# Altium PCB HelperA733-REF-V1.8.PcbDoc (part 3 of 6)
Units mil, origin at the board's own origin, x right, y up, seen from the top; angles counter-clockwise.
Board outline 5905.51 x 4133.86 mil, 2 copper layers (Top, Bottom), stack 12.7 mil thick; 475 components, 355 nets, 1867 pads, 1471 vias.
Unrouted connection lines stored in the file: 1178.
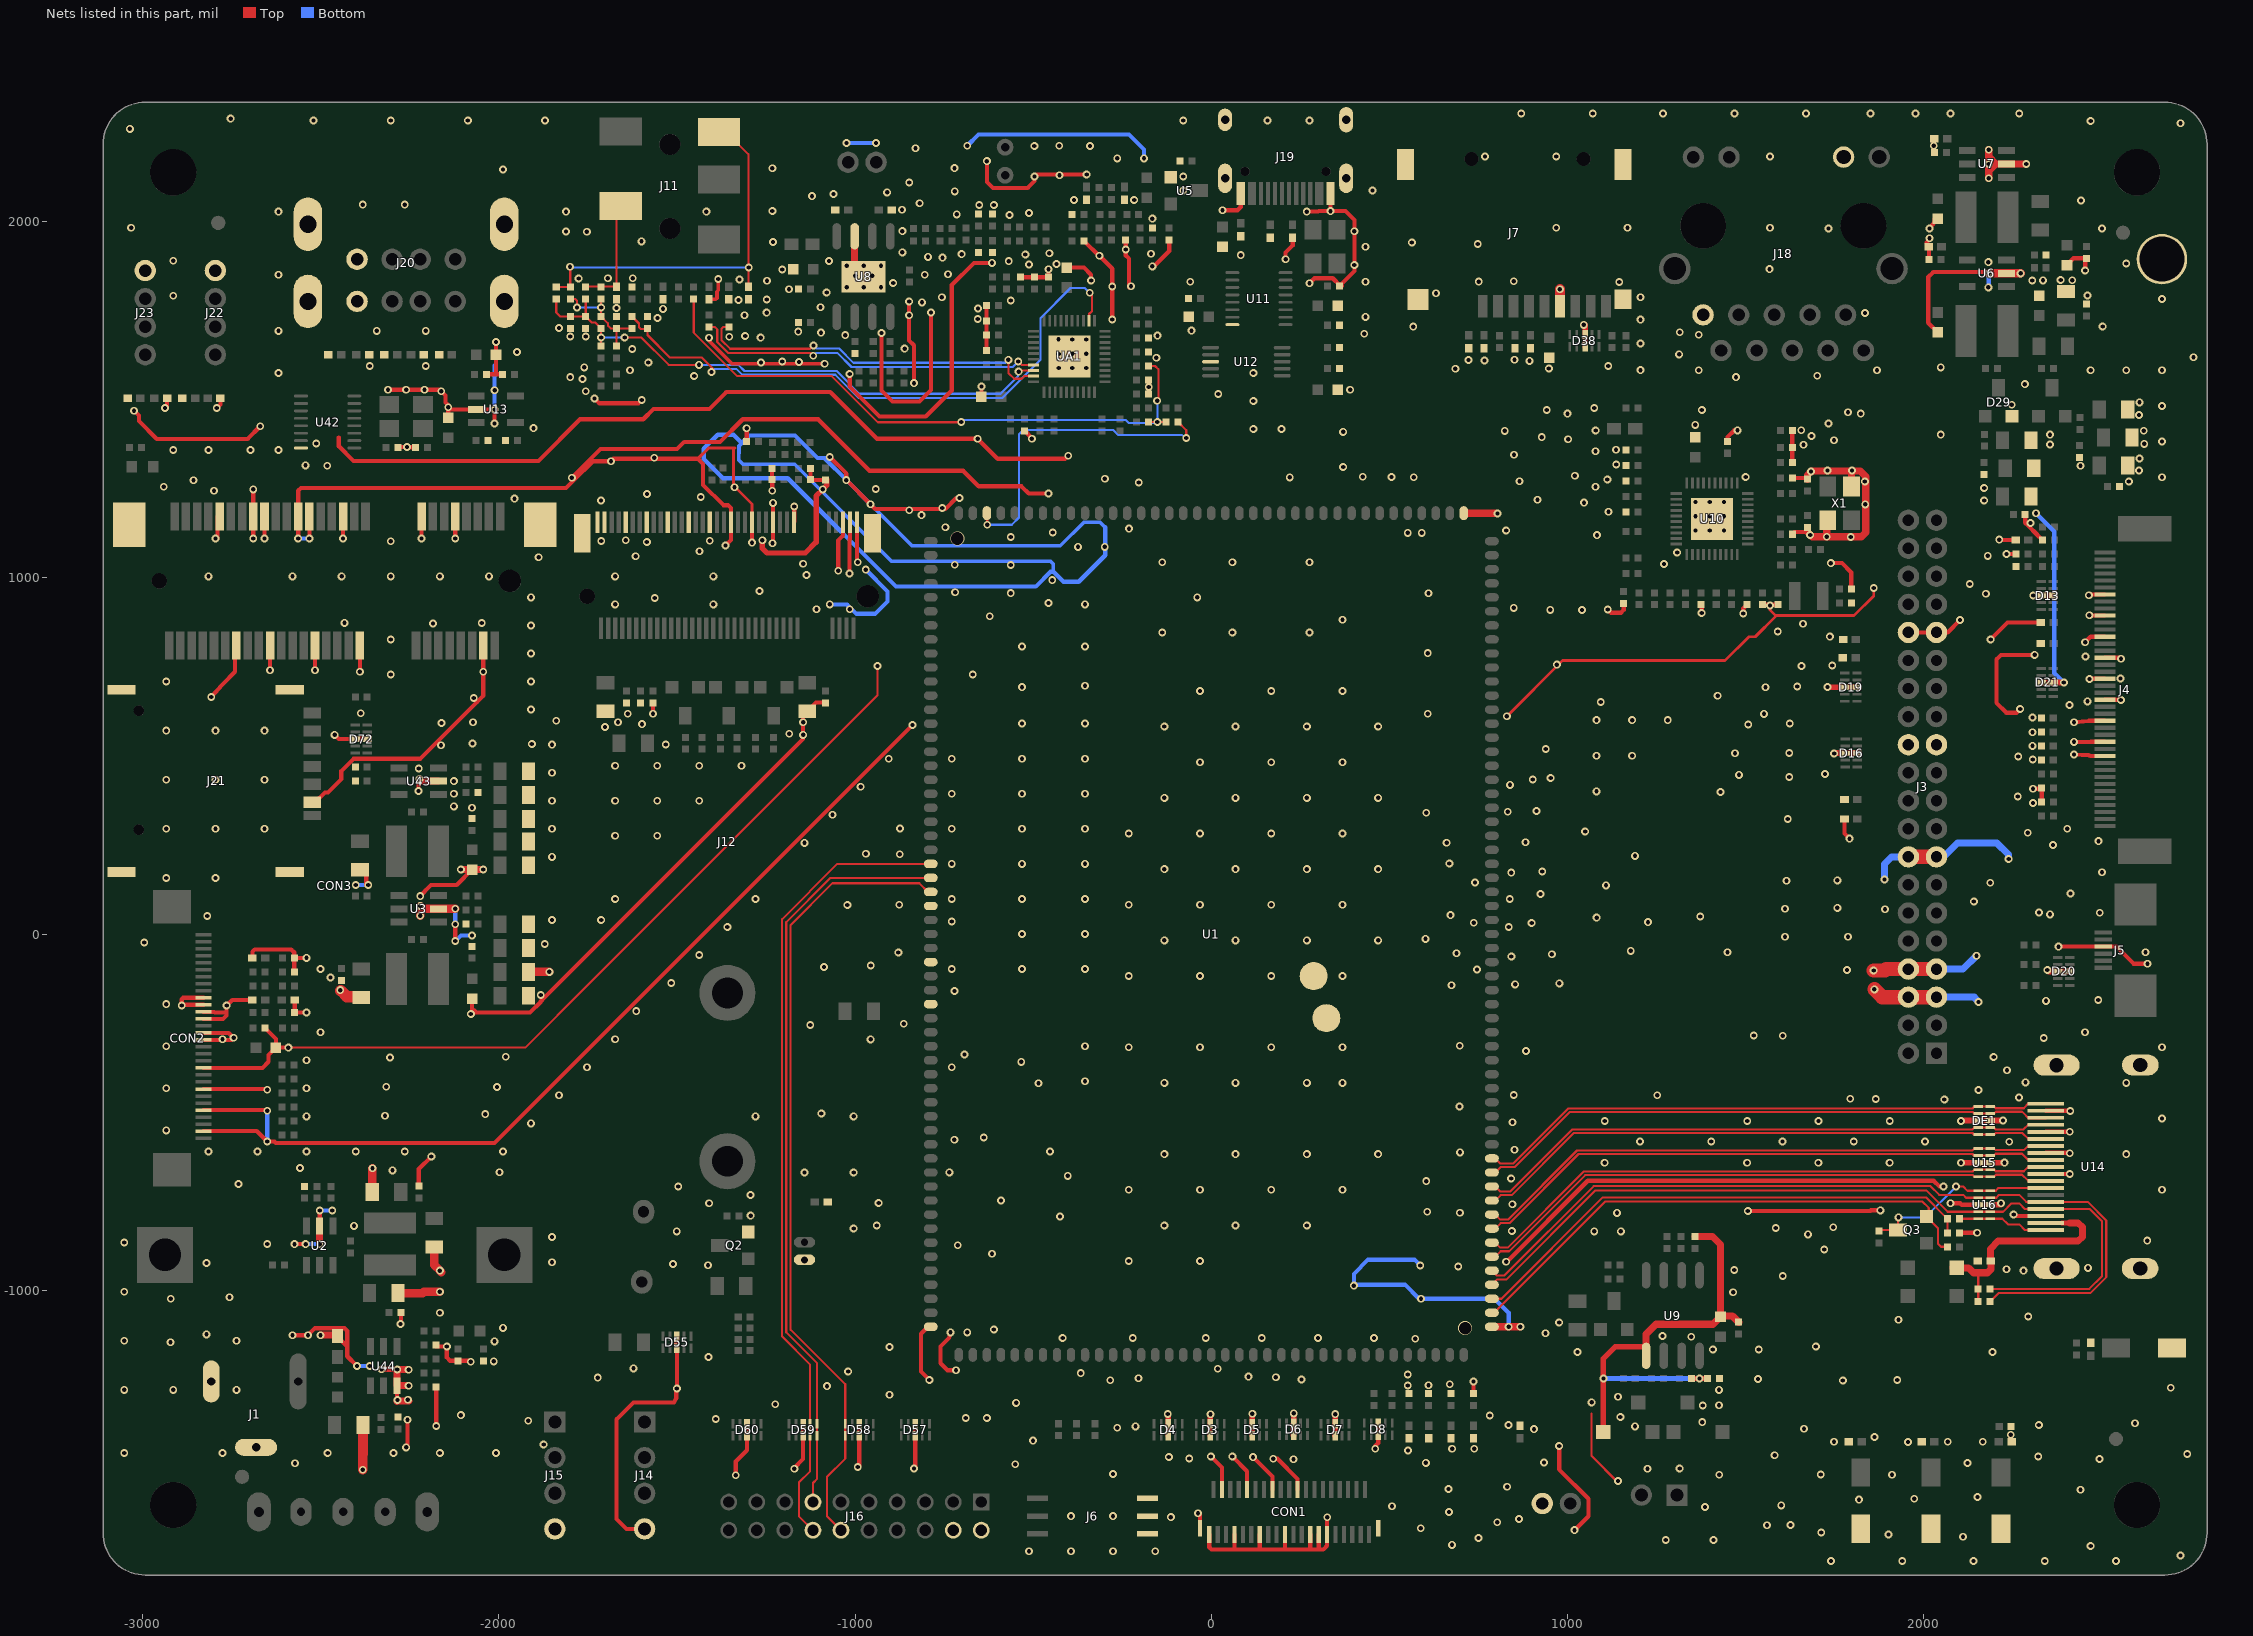
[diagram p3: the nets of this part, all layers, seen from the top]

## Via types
v1: diameter 22, hole 12, Top to Bottom, 1469 vias
v2: diameter 39.37, hole 35.43, Top to Bottom, 2 vias

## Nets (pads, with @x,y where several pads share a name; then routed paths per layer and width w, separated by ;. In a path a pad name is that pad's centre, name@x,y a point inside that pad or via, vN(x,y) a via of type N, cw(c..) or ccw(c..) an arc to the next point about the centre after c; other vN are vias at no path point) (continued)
GND: C2.2 C3.2 C5.2 C6.2 C7.2 C9.2 C10.2 C12.2 C13.2 C19.1 C20.1 C26.1 C27.2 C30.2 C31.2 C32.2 C33.1 C34.2 C35.2 C37.1 C38.2 C39.2 C40.2 C41.2 C42.2 C43.2 C44.2 C45.1 C46.2 C47.2 C49.2 C51.2 C54.1 C57.2 C58.2 C62.1 C63.1 C64.2 C65.2 C66.2 C67.2 C68.2 C69.2 C70.2 C71.2 C84.2 C86.2 C87.2 C88.2 C90.2 C91.2 C93.2 C94.2 C95.2 C96.2 C97.2 C98.2 C99.2 C100.2 C101.2 C102.2 C103.2 C323.1 C324.2 CA1.1 CA2.2 CA3.1 CA4.1 CA5.1 CA10.2 CA11.2 CA12.2 CA13.2 CA14.2 CA15.2 CA16.1 CA17.2 CA18.2 CA20.1 CA26.2 CB1.1 CB2.1 CB3.1 CB6.1 CB7.1 CB8.1 CB9.1 CE1.1 CE2.1 CE3.1 CE4.1 CE5.1 CE6.1 CE7.1 CE8.1 CE9.1 CE10.1 CE11.1 CE12.1 CE13.1 CE14.1 CE15.1 CL1.2 CON1.1 CON1.4 CON1.7 CON1.10 CON1.13 CON1.16 CON1.19 CON1.22 CON1.25 CON1.27 CON1.29 CON1.40 CON1.41 CON2.2 CON2.5 CON2.8 CON2.11 CON2.15 CON2.16 CON2.18 CON2.19 CON2.20 CON2.21 CON3.4 CON3.9 CON3.15 CON3.18 CON3.21 CON3.26 CON3.27 CON3.29 CON3.34 CON3.35 CON3.37 CON3.40 CON3.43 CON3.M1 CON3.M2 CP1.2 CP2.2 CP3.2 CP4.2 CU1.1 CU2.1 CU3.1 D3.3 D3.8 D4.3 D4.8 D5.3 D5.8 D6.3 D6.8 D7.3 D7.8 D8.3 D8.8 D9.1 D10.1 D11.1 D12.1 D13.3 D13.8 D15.1 D16.3 D16.8 D17.1 D18.1 D19.3 D19.8 D20.3 D20.8 D21.3 D21.8 D22.2 D23.2 D24.2 D25.2 D27.1 D28.2 D29.2 D30.2 D33.1 D34.1 D35.1 D36.1 D37.1 D38.3 D38.8 D39.2 D40.1 D41.1 D42.2 D43.1 D44.1 D45.1 D46.1 D47.1 D48.1 D49.1 D50.1 D55.3 D55.8 D57.3 D57.8 D58.3 D58.8 D59.3 D59.8 D60.3 D60.8 D61.2 D62.2 D63.2 D64.1 D65.2 D66.2 D67.2 D68.2 D71.2 D72.3 D72.8 D76.2 D77.2 D78.2 D79.2 D80.2 D81.2 D82.2 D83.2 DA1.1 DA2.1 DE1.3 DE1.8 FID5.1 J1.2 J1.3 J3.5 J3.6 J3.7 J3.8 J3.15 J3.16 J3.23 J3.24 J3.31 J3.32 J4.7 J4.10 J4.13 J4.16 J4.19 J4.22 J4.25 J4.28 J4.30 J5.3 J6.4 J6.5 J6.6 J7.6 J7.10 J7.11 J7.12 J7.13 J8.1 J9.2 J12.1 J12.3 J12.9 J12.15 J12.21 J12.27 J12.33 J12.39 J12.45 J12.51 J12.57 J12.71 J12.73 J12.75 J12.76 J12.77 J14.4 J15.4 J16.2 J16.4 J18.10 J18.12 J19.13 J19.14 J19.15 J19.16 J19.A1 J19.B1 J20.4 J20.8 J20.9 J20.10 J20.11 J20.12 J21.5 J21.8 J21.9 J21.10 J21.11 J22.1 J23.1 K1.2 K2.1 K3.1 K4.2 Q2.2 R6.1 R7.2 R11.2 R18.2 R20.1 R32.1 R34.2 R35.2 R36.2 R37.1 R41.1 R42.2 R43.2 R44.2 R45.2 R46.2 R47.2 R55.1 R65.2 R67.2 R75.2 R83.1 R92.2 R116.2 R118.2 R156.2 R158.2 R234.2 R235.2 R239.1 R241.1 R333.2 R334.2 RA2.1 RA4.2 RA12.2 RA26.2 RA27.2 RA30.1 RE4.1 RE14.1 RE15.1 RL2.1 RU1.1 RU2.1 U1.38 U1.95 U1.158 U1.162 U1.165 U1.188 U1.189 U1.190 U2.2 U3.2 U5.1 U6.2 U7.2 U8.7 U8.9 U10.41 U11.8 U12.3 U13.2 U14.2 U14.5 U14.8 U14.11 U14.17 U14.20 U14.21 U14.22 U14.23 U15.3 U15.8 U16.3 U16.8 U42.8 U43.2 U44.6 UA1.41 X1.2 X1.4 | length 44515.1
  Top w5: v1(-428.85,1669.23) -398.43,1638.81 UA1.41@-398.43,1621.09
  Top w6: v1(-2590.55,-318.9) -1925.2,-318.9 -1834.65,-228.35 -1834.65,-227.53 -937.01,670.1 v1(-937.01,751.97) ; 1067.52,-1346.23 1067.52,-1465.16 1141.73,-1539.37 v1(1141.73,-1535.43)
  Top w8: -1441.22,1333.93 -1410.74,1364.41 -1341.13,1364.41 ; -1336.41,1364.41 -1341.13,1364.41 ; J12.45@-1289.37,1155.5 -1289.37,1207.05 -1341.13,1258.81 -1341.13,1364.41 ; v1(829.64,611.41) 985.57,767.34 1010.2,767.34 1442.33,767.33 1509.16,834.16 1526.77,834.16 1583.87,891.26 1583.87,893.66 ; v1(1568.32,922.2) 1568.32,909.2 1583.87,893.66 ; v1(1859.19,971.14) 1859.19,948.77 1804.08,893.66 1583.87,893.66
  Top w10: v1(-1409.87,1673.56) -1409.87,1664.87 -1345.47,1600.47 v1(-1085.28,1600.47) ; D48.1@-1409.45,1781.21 -1390.96,1781.21 -1387.33,1784.84 -1387.33,1802.85 -1383.63,1806.55 -1383.63,1838.57 v1(-1383.86,1838.8) ; v1@-1353.3,1677.14 -1352.97,1676.81 v1(-1352.97,1676.48)
  Top w11.81: v1(-3023.62,1468.5) -3010.13,1455.01 -3010.13,1439.89 -2960,1389.76 -2704.72,1389.76 v1(-2669.29,1425.2) ; v1(-2937.01,1476.38) -2935.04,1474.41 -2930.82,1478.63 D78.2@-2930.82,1503.94 ; CON2.2@-2828.74,-553.15 -2679.13,-553.15 v1(-2649.61,-582.68) -2629.62,-582.68 -2625.68,-586.61 -2011.81,-586.61 v1(-838.58,586.61) ; CON2.5@-2828.74,-494.09 -2647.64,-494.09 v1(-2649.61,-496.06) ; CON2.8@-2828.74,-435.04 -2647.64,-435.04 v1(-2649.61,-437.01) ; CON2.11@-2828.74,-375.98 -2663.41,-375.98 -2646.12,-358.7 -2646.12,-339.43 C27.2@-2625.59,-318.9 ; CON2.15@-2828.74,-297.24 -2750,-297.24 v1(-2744.09,-291.34) -2757.87,-277.56 CON2.16@-2828.74,-277.56 ; CON2.18@-2828.74,-238.19 -2773.62,-238.19 -2763.78,-228.35 -2763.78,-220.47 ; CON2.19@-2828.74,-218.5 -2799.2,-218.5 -2797.23,-220.47 -2763.78,-220.47 ; CON2.20@-2828.74,-198.82 -2887.8,-198.82 v1(-2889.76,-200.79) -2889.76,-183.07 -2885.83,-179.13 CON2.21@-2828.74,-179.13 ; v1(-2807.09,665.35) -2775.59,700.56 -2740.16,735.99 -2740.16,810.04 CON3.40@-2736.22,810.04 ; v1(-2795.28,1110.24) -2789.46,1110.24 -2789.46,1172.24 CON3.43@-2783.47,1172.24 ; v1(-2791.34,1476.38) -2781.21,1486.5 D76.2@-2781.21,1503.94 ; D15.1@-2691.23,-185.04 -2748.03,-185.04 v1(-2763.78,-200.79) -2763.78,-220.47 ; D18.1@-2691.23,-66.93 -2691.23,-49.5 -2685.04,-43.31 -2582.68,-43.31 -2574.8,-51.18 -2573.82,-51.18 RL2.1@-2573.82,-66.93 ; v1(-2688.98,1110.24) v1(-2688.98,1248.03) ; v1(-2657.48,1110.24) CON3.35@-2657.48,1172.24 ; C26.1@-2656.5,-263.78 -2625.59,-294.69 C27.2@-2625.59,-318.9 ; v1(-2641.73,740.16) CON3.34@-2641.73,810.04 ; v1(-2590.55,-318.9) C27.2@-2625.59,-318.9 ; v1(-2578.74,-1125.98) v1(-2535.43,-1125.98) -2515.75,-1106.3 -2433.07,-1106.3 -2425.1,-1114.27 -2425.1,-1157.57 ; R20.1@-2573.82,-220.47 R20.1@-2572.55,-220.47 ; CL1.2@-2573.82,-106.3 RL2.1@-2573.82,-66.93 ; v1(-2573.43,-870.46) v1(-2541.93,-870.46) ; D17.1@-2572.55,-185.04 R20.1@-2572.55,-220.47 ; v1(-2562.99,1110.24) CON3.29@-2562.99,1172.24 -2562.99,1244.09 -2555.12,1251.97 -1811.02,1251.97 -1788.55,1274.45 -1736.22,1326.77 v1(-1685.04,1326.77) -1677.88,1333.93 -1441.22,1333.93 -1426.29,1319 -1426.29,1260.69 -1369.33,1203.73 -1356.65,1203.73 -1348.43,1195.51 J12.39@-1348.43,1155.5 -1348.43,1105.66 v1(-1363.54,1090.55) ; v1(-2539.37,-220.47) R20.1@-2572.55,-220.47 ; v1(-2539.37,-66.93) RL2.1@-2573.82,-66.93 ; v1(-2531.5,1110.24) CON3.27@-2531.5,1172.24 ; J21.5@-2523.62,370.08 -2515.16,370.08 -2487.65,397.59 -2478.97,397.59 -2441.79,434.77 -2441.79,457.31 -2407.38,491.72 -2220.59,491.72 -2060.14,652.17 -2043.31,669.01 v1(-2043.31,736.22) CON3.4@-2043.31,810.04 ; v1(-2515.75,740.16) CON3.26@-2515.75,810.04 ; U2.2@-2502.56,-819.28 v1(-2502.56,-775.97) ; v1(-2460.63,559.06) -2448.82,547.24 D72.8@-2402.87,547.24 -2402.87,549.21 -2368.79,549.21 D72.3@-2368.79,547.24 ; R156.2@-2452.76,-1125.98 -2452.76,-1129.92 -2425.1,-1157.57 ; -2448.82,1393.7 -2448.82,1369.13 -2407.64,1327.95 -1888.58,1327.95 -1771.65,1444.88 -1594.46,1444.88 -1565.5,1473.84 -1408.66,1473.83 -1361.26,1521.23 -1069.51,1521.23 -938.45,1390.17 v1(-655.88,1390.17) -599.47,1333.76 -410.33,1333.76 v1(-401.57,1342.52) ; v1(-2444.88,-157.48) v1@-2443.24,-159.13 ; v1(-2437.01,1110.24) CON3.21@-2437.01,1172.24 ; v1(-2397.64,-1212.6) -2425.1,-1185.13 -2425.1,-1157.57 ; C90.2@-2389.76,180.47 -2371.72,180.47 -2371.72,137.8 v1(-2366.14,137.8) ; v1(-2389.76,736.22) CON3.18@-2389.76,810.04 ; v1(-2311.02,1527.56) v1(-2259.84,1527.56) v1@-2212.6,1527.56 ; U44.6@-2285.43,-1267.72 -2285.43,-1311.5 -2285.43,-1312.53 v1(-2284.2,-1308.18) v1@-2284.16,-1311.26 ; C86.2@-2282.48,1366.14 -2282.48,1366.86 v1(-2257.56,1366.86) -2256.84,1366.14 C87.2@-2233.27,1366.14 ; v1(-2275.59,-1094.49) -2274.61,-1093.5 C3.2@-2274.61,-1062.99 ; v1(-2259.84,-1440.94) -2256.04,-1437.01 v1(-2256.04,-1363.52) ; v1(-2225.4,401.26) -2225.4,428.15 -2224.41,429.13 v1(-2222.31,435.5) ; C7.2@-2224.41,-707.68 -2224.41,-659.78 v1(-2189.19,-624.56) ; v1(-2220.47,106.3) -2206.67,120.1 -2206.67,121.19 -2190.07,137.8 -2117.72,137.8 C94.2@-2074.8,180.71 ; v1(-2216.54,1110.24) CON3.15@-2216.54,1172.24 ; -2213.86,-1007.87 -2209.92,-1003.94 ; R239.1@-2176.18,-1271.65 -2176.18,-1283.31 -2175.62,-1283.87 v1(-2175.62,-1380.63) ; R158.2@-2176.18,-1153.54 -2176.18,-1157.48 v1(-2145.67,-1157.48) -2145.67,-1188.98 -2136.81,-1197.83 R6.1@-2114.17,-1197.83 -2081.69,-1197.83 v1(-2078.74,-1200.79) ; C84.2@-2141.73,1449.21 v1(-2141.73,1478.56) ; v1(-2122.05,-19.69) v1(-2122.05,27.56) ; v1(-2122.05,1110.24) CON3.9@-2122.05,1172.24 ; v1(-2078.2,-224.25) v1@-2074.8,-220.86 ; C13.2@-2074.8,-181.5 -2074.8,-208.66 ; CU3.1@-2034.45,1570.87 -2003.94,1570.87 ; v1(-2011.81,1433.07) -2011.54,1433.34 v1(-2011.54,1472.44) U13.2@-2062.99,1472.44 -2135.61,1472.44 v1(-2141.73,1478.56) ; v1(-2007.87,1661.42) CU2.1@-2007.48,1625.98 -2007.48,1574.41 -2003.94,1570.87 ; CU1.1@-1989.17,1570.87 -2003.94,1570.87 ; v1(-1794.84,1280.74) -1714.48,1361.1 -1499.52,1361.1 -1479.54,1381.08 -1378.68,1381.08 -1315.03,1444.72 -1103.4,1444.72 -959.03,1300.35 -696.46,1300.35 -652.67,1256.56 -532.62,1256.56 -512.28,1236.22 v1(-456.69,1236.22) ; v1(-1731.1,1502.89) -1718.18,1489.97 -1607.43,1489.97 v1(-1598.49,1498.91) ; J14.4@-1590.55,-1669.69 -1641.34,-1669.69 -1669.29,-1641.73 -1669.29,-1362.2 -1622.05,-1314.96 -1507.87,-1314.96 -1501.97,-1303.15 -1501.97,-1277.56 v1(-1500,-1275.59) D55.8@-1500,-1162.71 -1501.97,-1162.71 -1501.97,-1128.63 D55.3@-1500,-1128.63 ; v1(-1566.93,618.11) CB6.1@-1566.93,648.62 ; v1(-1334.62,-1518.94) -1334.62,-1480.39 -1303.15,-1448.92 D60.8@-1303.15,-1408.38 D60.3@-1303.15,-1374.3 ; CB9.1@-1304.13,1381.89 v1(-1304.13,1419.73) ; v1(-1289.42,1098.49) -1289.37,1116.48 J12.45@-1289.37,1155.5 ; R234.2@-1233.27,1307.09 R334.2@-1233.27,1275.59 -1233.27,1268.21 -1232.28,1267.22 v1(-1232.28,1244.09) ; v1(-1231.36,1096.76) -1230.32,1096.76 J12.51@-1230.32,1155.5 v1(-1230.32,1210.13) ; J12.57@-1171.26,1155.5 -1171.26,1157.48 -1170.61,1157.48 v1(-1170.61,1200.14) ; v1(-1170.25,-1500.8) -1170.25,-1498.07 -1145.67,-1473.49 D59.8@-1145.67,-1408.38 D59.3@-1145.67,-1374.3 ; R235.2@-1125,1307.09 R333.2@-1125,1275.59 -1124.02,1274.61 CB8.1@-1082.68,1274.61 ; CB1.1@-1082.68,648.62 -1082.68,649.76 -1109.45,649.76 CB3.1@-1133.86,625.35 -1140.73,625.35 -1145.67,620.42 v1(-1145.67,594.49) v1(-1145.67,559.06) -1145.67,547.24 -1872.88,-179.96 -1881.89,-188.98 -1881.89,-190.28 -1912.09,-220.47 -2062.99,-220.47 ; v1(-1070.87,1338.58) -1024.43,1292.15 v1(-1024.43,1273.9) v1(-956.66,1206.13) -943.41,1192.88 -746.55,1192.88 -716.01,1223.42 v1(-706.75,1223.57) ; v1(-1047.24,1019.68) -1047.29,1104.2 -1033.47,1118.02 J12.71@-1033.47,1155.5 ; v1(-1015.75,1011.81) -1015.75,1107.05 -1013.78,1107.05 J12.73@-1013.78,1155.5 ; v1(-1015.07,1572.15) -1015.07,1536.62 -931.14,1452.69 -801.43,1452.69 -728.44,1525.68 -728.44,1821.55 -666.22,1883.76 v1(-615.29,1883.76) ; J12.75@-994.1,1155.5 -994.1,1043.31 v1(-992.13,1043.31) ; v1(-992.13,-1496.06) -988.19,-1492.13 D58.8@-988.19,-1408.38 D58.3@-988.19,-1374.3 ; v1(-925.74,1686.91) -925.74,1525.65 -894.73,1494.65 -819.41,1494.65 -786.92,1527.14 v1(-786.92,1744.27) ; v1(-848.09,1736.91) v1@-848.1,1734.99 ; v1(-848.1,1775.31) v1@-848.1,1734.99 ; v1(-834.65,-1500) -830.71,-1500 D57.8@-830.71,-1408.38 D57.3@-830.71,-1374.3 ; v1(-834.52,1546.22) -834.52,1652.7 -848.1,1666.28 v1@-848.1,1734.99 ; v1(-791.34,-1251.97) -814.96,-1228.35 -814.96,-1122.05 -795.28,-1102.36 U1.188@-787.4,-1102.36 ; v1(-732.28,-1118.11) -736.22,-1133.86 -759.84,-1157.48 -759.84,-1204.72 -740.16,-1224.41 v1(-716.54,-1224.41) ; CA18.2@-646.06,1507.87 -644.89,1507.87 v1(-644.89,1536.51) ; CA10.2@-630.91,1637.8 CA2.2@-630.91,1681.1 RA2.1@-630.91,1720.47 CA3.1@-630.91,1763.78 ; v1(-629.92,2169.29) -629.92,2110.98 -613.11,2094.16 -515.45,2094.16 -496.06,2113.55 v1(-496.06,2125.98) -490.13,2131.92 v1(-349.84,2131.92) ; CA14.2@-535.43,1843.5 RA4.2@-496.06,1843.5 RA26.2@-456.82,1843.5 ; CA13.2@-523.62,1412.4 -519.68,1412.4 -519.68,1408.46 v1(-503.65,1390.21) ; v1(-456.82,1865.75) RA26.2@-456.82,1843.5 ; RA26.2@-456.69,1843.5 RA26.2@-456.82,1843.5 ; CA1.1@-405.51,1870.47 -357.23,1870.47 -337.27,1850.51 v1(-337.27,1834.16) ; RA12.2@-357.28,1944.88 -357.28,1945.36 -356.81,1945.36 -314.63,1903.18 v1(-314.13,1903.68) -277.9,1867.45 v1@-277.9,1818.49 ; v1(-278.12,1817.3) v1@-277.9,1817.3 ; v1(-277.9,1724.8) v1@-277.9,1817.3 ; CA5.1@-240.16,1947.83 v1(-240.16,1921.26) -240.16,1904.27 -231.39,1895.5 -231.39,1815.42 -228.64,1818.17 v1(-225.59,1818.17) ; v1(-165.35,1874.02) -161.42,1874.02 -118.11,1917.32 C20.1@-118.11,1947.83 ; v1(-37.29,-1625.88) -31.37,-1631.81 CON1.41@-31.37,-1667.78 ; CON1.1@-5.78,-1685 -5.78,-1721.25 0.59,-1727.62 65.09,-1727.62 ; v1(-1.26,-1466.74) 29.65,-1497.65 CON1.4@29.65,-1559.02 ; v1(31.43,2031.39) 73.52,2031.39 82.68,2040.55 J19.B1@82.68,2078.74 ; v1(59.1,-1466.48) 100.52,-1507.9 CON1.10@100.52,-1559.02 ; CON1.7@65.09,-1685 65.09,-1727.62 ; v1(116.81,-1468.29) 171.39,-1522.87 CON1.16@171.39,-1559.02 ; CON1.13@135.95,-1685 135.95,-1727.62 ; v1(174,-1472.94) 185.7,-1472.94 242.25,-1529.49 CON1.22@242.25,-1559.02 ; CON1.19@206.82,-1685 206.82,-1727.62 ; v1(208.66,1893.7) 208.66,1912.93 228.35,1932.62 D61.2@228.35,1954.44 ; v1(267.72,2027.56) 300.48,2027.56 301.88,2028.95 v1(334.65,2028.95) ; v1(275.59,1826.77) 289.46,1840.65 340.96,1840.65 C64.2@360.98,1820.63 ; CON1.25@277.68,-1685 277.68,-1727.62 ; CON1.27@301.31,-1685 301.31,-1727.62 ; v1(325.62,-1637.15) 324.93,-1637.15 CON1.29@324.93,-1685 324.93,-1717.14 314.45,-1727.62 301.31,-1727.62 ; J19.A1@334.65,2078.74 v1(334.65,2028.95) ; C64.2@366.14,1818.9 C64.2@359.25,1818.9 ; v1(460,-1444.66) 460,-1437.42 468.5,-1428.91 D8.8@468.5,-1406.8 D8.3@468.5,-1372.72 ; CP4.2@736.22,-1290.35 v1(736.22,-1255.91) ; v1(827.63,-919.75) 829.57,-919.75 1056.76,-692.56 2027.56,-692.56 2043.66,-708.66 v1(2055.12,-708.66) ; v1(976.38,-1437.01) 976.38,-1502.55 1059.06,-1585.23 1059.06,-1634.4 1019.95,-1673.5 v1(1019.69,-1673.23) ; v1(1112.63,911) 1122.05,901.57 1149.61,901.57 1157.48,909.45 CE2.1@1157.48,928.15 ; RE15.1@1374.02,924.21 1376.38,924.21 v1(1376.38,900.74) ; CE5.1@1448.82,1382.87 1448.82,1394.63 1467.92,1413.73 v1(1476.99,1413.73) ; v1(1493.11,899.35) 1493.11,913.38 RE14.1@1503.94,924.21 ; v1(1506.07,-777.19) 1850.39,-777.19 1851.99,-775.59 v1(1877.95,-775.59) ; CE10.1@1547.24,924.21 CE12.1@1590.55,924.21 ; R83.1@1630.91,1122.05 1637.01,1128.15 1672.99,1128.15 ; CE1.1@1630.91,1279.53 1673.17,1279.53 1673.23,1279.53 CE14.1@1673.23,1276.57 ; RE4.1@1630.91,1322.83 CE9.1@1630.91,1366.14 C62.1@1630.91,1413.39 ; v1(1739.01,1041) 1770.17,1041 1796.26,1014.91 CE3.1@1796.26,968.5 ; D82.2@1777.28,322.83 1777.28,281.78 v1(1791.34,267.72) ; J3.32@1956.69,846.46 J3.31@2035.43,846.46 2067.07,846.46 v1(2101.72,881.1) ; R41.1@2014.76,1893.7 2014.76,1934.05 2007.87,1940.94 2017.72,1950.79 v1(2015.75,1952.76) ; v1(2015.75,1980.31) 2030.32,1998.43 2030.32,2007.48 C44.2@2039.37,2007.48 ; v1(2027.56,2212.6) 2027.56,2232.28 D23.2@2029.24,2232.28 ; C38.2@2039.37,1688.58 2012.5,1715.45 2012.5,1844.2 2026.57,1858.27 2178.35,1858.27 v1(2182.28,1854.33) ; v1(2074.8,-755.91) 2102.36,-755.91 2106.3,-759.84 U16.3@2152.25,-759.84 U16.8@2186.33,-759.84 ; R92.2@2099.41,-838.58 v1(2149.61,-838.58) ; v1(2187.44,826.56) 2234.89,874.02 D80.2@2328.46,874.02 ; v1(2211.63,1106.93) 2211.63,1106.3 D28.2@2257.59,1106.3 ; v1(2232.28,1066.93) C33.1@2258.86,1066.93 ; v1(2244.09,-1405.51) 2244.09,-1425.2 D41.1@2246.35,-1425.2 ; v1(2251.97,-787.4) 2255.91,-791.34 U14.17@2342.52,-791.34 ; v1(2270.29,631.49) 2259.86,621.06 2231.47,621.06 2203.63,648.89 2203.63,770.92 2216.17,783.46 v1(2311.02,783.46) ; C35.2@2284.45,1177.17 2284.45,1154.35 v1@2292.27,1146.53 ; v1(2299.42,1153.67) v1@2292.27,1146.53 ; v1(2306.33,407.94) R34.2@2330.71,407.94 ; R35.2@2330.71,370.08 R34.2@2330.71,407.94 ; R34.2@2330.71,409.45 R34.2@2330.71,407.94 ; R36.2@2333.66,1106.3 2333.66,1105.55 2332.92,1105.55 2318.2,1120.27 2318.2,1120.6 v1@2292.27,1146.53 ; U14.11@2342.52,-673.23 2409.44,-673.23 v1(2409.54,-673.33) ; U14.8@2342.52,-614.17 2408.2,-614.17 v1(2409.45,-615.42) ; U14.5@2342.52,-555.12 2409.32,-555.12 v1(2409.39,-555.04) ; U14.2@2342.52,-496.06 2410,-496.06 v1(2410.73,-496.79) ; v1(2377.95,-35.43) J5.3@2503.94,-35.43 2540.38,-35.43 2588.21,-83.26 v1(2628.01,-83.26) ; C42.2@2401.57,1877.56 2401.57,1877.95 2420.28,1896.65 C43.2@2456.69,1896.65 2452.76,1892.72 v1(2452.76,1862.2) ; v1(2421.26,503.94) 2462.57,501.61 2467.84,500 J4.30@2507.87,500 ; v1(2421.26,539.37) 2463.3,538.56 2468.5,539.37 J4.28@2507.87,539.37 ; v1(2421.26,594.49) 2463.95,598.26 2463.95,598.43 J4.25@2507.87,598.43 ; v1(2452.76,818.9) 2468.5,834.65 J4.13@2507.87,834.65 ; v1(2463.07,950.93) 2468.17,952.76 J4.7@2507.87,952.76 ; v1(2464.58,894.57) 2466.94,893.7 J4.10@2507.87,893.7 ; v1(2464.76,715.67) 2469.58,716.54 J4.19@2507.87,716.54 ; J4.22@2507.87,657.48 2550.43,657.48 v1(2553.04,656.65) ; J4.16@2507.87,775.59 2548.54,775.59 v1(2553.44,772.41) ; v1@-2212.6,1527.56 v1(-2208.66,1527.56) ; v1@-2212.6,1527.56 -2208.66,1531.5 v1(-2208.66,1527.56) ; v1(-2208.66,1527.56) -2165.35,1527.56 v1(-2161.42,1523.62) -2149.61,1511.81 -2149.61,1492.13 -2141.73,1484.25 v1(-2141.73,1478.56) ; v1@-2074.8,-220.86 -2074.42,-220.47 -2062.99,-220.47 ; v1@-2074.8,-220.86 -2074.8,-208.66 ; -2074.8,-208.66 -2068.7,-214.76 -2062.99,-220.47 ; v1@-277.9,1817.3 -276.9,1817.3 -276.9,1817.49 v1@-277.9,1818.49 ; v1@-277.9,1817.3 v1@-277.9,1818.49 ; 65.09,-1727.62 135.95,-1727.62 ; 135.95,-1727.62 206.82,-1727.62 ; 206.82,-1727.62 277.68,-1727.62 ; 277.68,-1727.62 301.31,-1727.62 ; v1(334.65,2028.95) 376.56,2028.95 401.57,2003.94 v1(401.57,1972.44) v1(401.57,1877.95) 401.57,1861.22 C64.2@360.98,1820.63 ; C64.2@359.25,1818.9 C64.2@360.98,1820.63 ; C64.2@359.25,1818.9 359.25,1820.63 C64.2@360.98,1820.63
  Top w15: v1(-1260.04,1105.08) -1260.04,1082.54 -1246.92,1069.42 -1139.68,1069.42 -1109.11,1099.99 -1109.11,1229.47 v1(-1090.55,1248.03) -1078.74,1259.84 -1078.74,1271.65 -1082.68,1275.59 CB8.1@-1078.74,1275.59
  Top w15.75: v1(-2328.88,-1221.76) -2285.67,-1221.76 v1(-2284.85,-1222.58)
  Top w16: v1(-122.42,-1347) -121.04,-1348.38 D4.8@-121.04,-1374.26 D4.3@-121.04,-1408.34 ; D3.3@-2.93,-1408.34 D3.8@-2.93,-1374.26 -2.93,-1348.67 v1(-2.4,-1348.14) ; D5.3@115.18,-1408.34 115.18,-1376.48 115.26,-1376.4 v1(115.26,-1346.62) ; D6.3@231,-1407.45 231,-1375.51 231.3,-1375.22 v1(231.3,-1345.37) ; D7.3@347.47,-1408.34 347.47,-1377.07 347.81,-1376.73 v1(347.81,-1347.55) ; v1(1045.61,1709.81) 1049.21,1709.81 D38.8@1049.21,1682.68 D38.3@1049.21,1648.23 ; v1(1729.75,693.39) 1730.22,692.91 D19.8@1778.24,692.91 D19.3@1812.32,692.91 ; v1(1748.25,506.79) 1749.33,507.87 D16.8@1779.22,507.87 D16.3@1813.3,507.87 ; v1(2103.97,-642.08) 2104.32,-641.73 U15.3@2152.25,-641.73 U15.8@2186.33,-641.73 v1(2226.33,-641.73) ; v1(2104.26,-524.53) 2105.17,-523.62 DE1.3@2152.25,-523.62 DE1.8@2186.33,-523.62 v1(2222.25,-523.62) ; U16.8@2186.33,-759.84 2216.54,-759.84 v1(2216.54,-755.91) ; v1(2307.12,950.02) v1(2307.12,950.02) D13.3@2329.42,950.11 D13.8@2363.5,950.11 ; D21.3@2329.42,706.02 D21.8@2363.5,706.02 v1@2392.91,706.02 ; v1(2346.73,-101.22) 2350.56,-105.06 D20.3@2375.45,-105.06 D20.8@2409.53,-105.06
  Top w19.68: v1(-2502.56,-870.46) U2.2@-2502.56,-819.28 ; v1(-2500,-1125.98) R156.2@-2452.76,-1125.98 ; v1@-2285.43,-1311.5 v1(-2284.2,-1308.18) ; v1@-2284.16,-1311.26 -2251.34,-1311.26 v1(-2255.04,-1307.43) ; v1(-2252.91,-1267.72) U44.6@-2285.43,-1267.72 -2285.43,-1222.58 v1(-2284.85,-1222.58) -2284.85,-1222.75 -2252.86,-1222.75 v1(-2252.86,-1222.92) ; v1(-2222.31,435.5) -2220.47,433.07 -2216.54,429.13 U43.2@-2169.29,429.13 ; v1@-2105.91,180.71 -2094.49,180.71 -2094.09,181.1 v1(-2043.31,181.1) ; U7.2@2232.28,2161.42 v1(2287.4,2161.42)
  Top w20: U8.7@-1001.07,1958.16 -1001.07,1874.1 -999.28,1872.31 v1(-999.28,1847.55) ; U1.95@708.66,1181.1 796.11,1181.1 v1(803.53,1180.38) ; U1.38@787.4,-1102.36 v1(867.4,-1102.36) ; CE15.1@1673.23,1140.75 1672.99,1128.15 1686.18,1114.96 v1@1727.41,1114.96 ; CE14.1@1673.23,1276.57 1673.17,1279.53 1672.99,1288.34 1682.79,1298.15 1684.11,1299.47 v1@1797.24,1299.47 ; v1(1727.41,1114.81) v1@1727.41,1114.96 ; X1.2@1730.32,1161.42 1727.41,1158.51 v1@1727.41,1114.96 ; X1.4@1797.24,1255.91 v1@1797.24,1299.47 ; v1(2182.28,2121.42) 2182.28,2141.42 ; v1(2182.28,2201.42) 2182.28,2181.42 ; U7.2@2232.28,2161.42 2202.28,2161.42 ; v1@1727.41,1114.96 1824.6,1114.96 1836.87,1127.23 1836.87,1284.09 1821.49,1299.47 v1@1797.24,1299.47 ; 2182.28,2141.42 2202.28,2161.42 ; 2182.28,2141.42 v1(2182.28,2161.42) ; v1(2182.28,2161.42) 2182.28,2181.42 ; v1(2182.28,2161.42) 2202.28,2161.42 ; 2182.28,2181.42 2202.28,2161.42
  Top w23.62: C6.2@-2354.96,-724.41 -2354.96,-658.11 v1(-2354.33,-657.48) ; C2.2@-2282.83,-1007.87 -2213.86,-1007.87 ; v1(-2220.47,51.18) v1@-2220.47,70.87 ; v1(-2220.47,78.74) v1@-2220.47,70.87 ; -2209.92,-1003.94 v1(-2165.35,-1003.94) ; C5.2@-2181.1,-878.58 -2181.1,-929.13 v1(-2165.35,-944.88) v1@-2161.42,-948.82 ; v1(-2122.05,70.87) -2137.8,70.87 U3.2@-2169.29,70.87 v1@-2220.47,70.87 ; C97.2@-1916.69,-106.3 v1(-1857.98,-106.3) ; v1(2182.28,1854.33) 2204.72,1854.33 U6.2@2232.28,1854.33 v1(2271.65,1854.33)
  Top w27.56: v1(-2381.89,-1503.94) -2381.89,-1460.65 -2381.26,-1460.02 C324.2@-2381.26,-1377.95
  Top w28: J7.6@978.35,1761.81 v1(978.35,1809.81)
  Top w31.5: v1@-2443.24,-159.13 -2426.58,-175.79 -2385.83,-175.79 C9.2@-2385.83,-177.8
  Top w40: v1(1859.04,-102.12) 1891.04,-102.12 1894.73,-98.43 J3.8@1956.69,-98.43 J3.7@2035.43,-98.43 ; v1(1861.17,-155.33) 1883,-177.17 J3.6@1956.69,-177.17 J3.5@2035.43,-177.17 ; J3.16@1956.69,216.54 J3.15@2035.43,216.54
  Bottom w10: -1325.77,1349.49 -1325.77,1329.57 -1314.46,1318.26 -1169.27,1318.26 -897.56,1046.55 -451.26,1046.55 -443.18,1038.47 -443.18,1016.96 ; v1(-956.66,1206.13) -840.14,1089.61 -423.59,1089.61 -357.99,1155.21 -311.54,1155.21 -298.65,1142.32
  Bottom w11.81: v1(-2649.61,-582.68) v1(-2649.61,-496.06) ; v1(-2562.99,1110.24) v1(-2531.5,1110.24) ; v1(-2541.93,-870.46) v1(-2502.56,-870.46) ; v1(-2502.56,-775.97) v1(-2467.13,-775.97) ; v1(-2401.57,137.8) v1(-2366.14,137.8) ; v1(-2397.64,-1212.6) v1(-2362.2,-1212.6) ; v1(-2122.05,-19.69) -2106.3,-3.94 v1(-2074.8,-3.94) ; v1(-2122.05,27.56) v1(-2122.05,70.87) ; v1(-2011.54,1472.44) v1(-2011.54,1526.08) -2011.54,1596.01 -2007.87,1599.68 v1(-2007.87,1661.42) ; -1325.77,1349.49 -1325.77,1369.95 -1317.77,1377.95 ; v1(-1070.87,925.2) -1023.62,925.2 v1(-1014.7,911.67) -1022.12,925.2 -995.62,898.7 -943.55,898.7 -908.93,933.32 -908.93,961.66 v1(-969.94,1022.66) ; v1(-1023.62,2220.47) v1(-940.94,2220.47) ; v1(-956.66,1206.13) v1(-1024.43,1273.9) -1085.73,1335.2 v1(-1070.87,1338.58) -1086.11,1336.08 -1105.52,1336.08 -1168.35,1398.91 -1296.81,1398.91 -1317.77,1377.95 ; v1(-685.04,2212.6) -653.45,2244.19 -231,2244.19 -188.98,2202.17 v1(-188.98,2177.17) ; v1(-428.85,1669.23) -391.2,1669.23 v1(-390.61,1668.64) ; -298.65,1142.32 -297.74,1141.41 -297.74,1063.05 -371.96,988.83 -415.05,988.83 -443.18,1016.96 -451.26,1016.96 -492.5,975.72 -885.35,975.72 -1188.98,1279.35 -1370.8,1279.35 -1424.48,1333.03 -1424.48,1362.21 -1385.25,1401.44 -1341.26,1401.44 -1317.77,1377.95 ; v1(586.64,-930.24) 570.5,-914.1 440.23,-914.1 400.18,-954.15 v1(400.18,-986.9) 402.83,-984.25 543.31,-984.25 582.68,-1023.62 795.28,-1023.62 834.65,-1062.99 v1(834.65,-1102.36) ; v1(1859.04,-102.12) v1@1862.73,-98.43 ; v1(2181.1,1814.96) 2182.28,1816.14 v1(2182.28,1854.33) ; v1(2314.96,1181.1) 2366.14,1129.92 2366.14,732.79 v1(2392.92,706.02)
  Bottom w19.68: v1(1861.17,-155.33) 1864,-155.33 1885.83,-177.17 1913.39,-177.17 J3.6@1956.69,-177.17 J3.5@2035.43,-177.17 2139.76,-177.17 ; v1@1862.73,-98.43 J3.8@1956.69,-98.43 2003.94,-98.43 J3.7@2035.43,-98.43 2110.24,-98.43 v1(2147.64,-61.02) ; v1(1889.34,153.32) 1889.34,196.42 1909.45,216.54 1925.2,216.54 J3.16@1956.69,216.54 1996.06,216.54 J3.15@2035.43,216.54 2055.12,216.54 2094.49,255.91 2204.72,255.91 2237.98,222.65 v1(2237.98,210.83) ; 2139.76,-177.17 v1(2153.54,-190.94) 2141.73,-177.17 2139.76,-177.17
  other v1: 1739.53,-1759.62 1939.53,-1759.62 2139.53,-1759.62 2339.53,-1759.62 2539.53,-1759.62 2720.47,-1744.09 -511.81,-1732.28 -393.7,-1732.28 -275.59,-1732.28 -157.48,-1732.28 2468.23,-1717.85 675.75,-1714.52 1275.59,-1700.79 1409.45,-1700.79 749.7,-1695.08 2109.61,-1691.78 1900.94,-1685.66 1712.04,-1680 587.98,-1667.88 1559.53,-1659.62 1625.49,-1658.82 802.47,-1651.16 863.57,-1642.11 -113.43,-1636.78 -393.7,-1633.86 -275.59,-1633.86 666.95,-1622.19 1385.99,-1608.46 507.24,-1606.08 1599.53,-1603.62 1818.03,-1587.68 1973.01,-1585.33 2150.66,-1580.34 2439.53,-1559.62 665.95,-1557.63 830.38,-1551.6 1910.36,-1517.97 1425.52,-1517.92 1710.44,-1517.13 -275.59,-1515.75 1224.03,-1500.7 1314.57,-1500.06 -550.07,-1488.19 -2571.64,-1485.54 2122.33,-1484.99 602.28,-1484.44 933.93,-1483.5 230.9,-1474.25 2492.85,-1473.39 -62.09,-1472.2 -119.09,-1467.87 2321.03,-1466.68 1581.13,-1462.79 2739.53,-1459.62 -3051.18,-1456.69 -2775.59,-1456.69 -2480.31,-1456.69 -2295.28,-1456.69 -2165.35,-1456.69 -2007.87,-1456.69 552.15,-1449.42 676.06,-1444.7 738.21,-1444.7 -1874.02,-1433.07 1955.42,-1426.09 1748.03,-1425.2 2066.93,-1425.2 2165.35,-1425.2 -500.68,-1421.97 1861.62,-1411.79 905.51,-1389.76 1663.81,-1388.66 -263.78,-1385.83 -212.6,-1381.89 1188.98,-1381.89 2322.83,-1377.95 833.97,-1377.88 2592.85,-1373.39 1377.95,-1370.08 -1917.32,-1366.14 -1391.08,-1361.09 -688.98,-1358.27 -629.92,-1358.27 1148.23,-1355.41 781.56,-1351.54 -2106.3,-1350.39 1379.53,-1323.62 1425.2,-1322.83 -1224.09,-1319.87 -547.83,-1315.9 1067.52,-1314.49 1141.79,-1298.95 -903.25,-1293.21 -3051.18,-1279.53 -2913.39,-1279.53 -2736.22,-1279.53 1425.2,-1279.53 2692.85,-1273.39 -1078.49,-1269.01 551.6,-1266.96 609.71,-1266.59 669.29,-1263.78 1772.71,-1253.26 -283.68,-1252.34 1925.2,-1251.97 253.36,-1250.63 1534.74,-1249.23 -204.22,-1246.74 -1722.12,-1245.24 181.27,-1244.15 104.43,-1242.42 551.18,-1236.22 -366.62,-1232.61 -1019.38,-1227.64 18.04,-1220.29 -1621.61,-1219.13 -2013.82,-1199.47 -1411.45,-1187.15 1027.56,-1173.23 2192.85,-1173.39 1536.53,-1166.25 1407.81,-1165.91 -903.25,-1159.45 1696.85,-1157.48 -2921.26,-1145.67 -2011.66,-1143.29 -3051.18,-1141.73 -2736.22,-1141.73 572.53,-1136 -417.32,-1133.86 -220.47,-1133.86 -15.75,-1133.86 141.73,-1133.86 299.21,-1133.86 456.69,-1133.86 1347.03,-1130.61 1266.43,-1128.58 -2820.47,-1123.62 937.87,-1120.56 -685.04,-1118.11 -610.24,-1110.24 -1988.25,-1105.46 976.38,-1090.55 1929.13,-1082.68 2292.85,-1073.39 -2165.35,-1062.99 -2920.47,-1023.62 588.77,-1023.9 -2755.91,-1019.69 1464.72,-1005.4 -3051.18,-1003.94 1603.93,-959.59 2279.53,-944.88 1467.69,-942.93 2232.28,-940.94 2460.63,-937.01 692.96,-933.24 -1412.63,-929.5 -1511.11,-925.93 -2820.47,-923.62 -1850.39,-921.26 -231.77,-917.85 -31.77,-917.85 -615.39,-897.52 1720.47,-885.83 -711.62,-873.75 -2649.61,-870.08 -3051.18,-866.14 2627.25,-860.66 -1850.39,-850.39 1674.84,-843.01 -1500.34,-834.57 1074.8,-834.65 1149.61,-834.65 843.64,-833.84 -1003.94,-826.77 1584.2,-825.11 1745.6,-822.99 -2406.29,-819.13 -938.91,-818.04 -131.77,-817.85 68.23,-817.85 268.23,-817.85 -424.54,-792.63 -1292.96,-790.5 697.72,-782.36 1138.85,-782.64 606.3,-779.53 845.03,-758.51 -1409.45,-755.91 -933.74,-754.77 -590.55,-748.03 -1293.26,-732.55 -231.77,-717.85 -31.77,-717.85 168.23,-717.85 368.23,-717.85 2668.23,-717.85 -1496.06,-708.66 -2730.74,-701.82 603.53,-693.62 841.57,-686.42 -403.12,-678.75 -1141.73,-669.29 -1003.94,-669.29 -735.16,-668.97 -1997.99,-668.58 -2298.31,-663.43 -2557.62,-656.91 1103.97,-642.08 1503.97,-642.08 1703.97,-642.08 1903.97,-642.08 -131.77,-617.85 68.23,-617.85 268.23,-617.85 468.23,-617.85 2568.23,-617.85 698.15,-612.84 -2814.96,-610.24 -2677.17,-610.24 -2539.37,-610.24 -2401.57,-610.24 -2263.78,-610.24 -1988.19,-610.24 -452.76,-610.24 850.96,-605.42 2239.76,-583.19 1203.3,-582.25 1403.3,-582.25 1603.3,-582.25 1803.3,-582.25 2003.3,-582.25 -721.22,-577.46 -638.86,-570.92 -2933.07,-551.18 -1909.45,-531.5 845.72,-528.25 1104.26,-524.53 1504.26,-524.53 1704.26,-524.53 1904.26,-524.53 2668.23,-517.85 -2539.37,-511.81 -1279.53,-511.81 -1003.94,-511.81 -2319.31,-510.3 -2037.71,-505.63 -1094.49,-503.94 696.85,-484.25 2057.55,-464.24 1864.95,-463.18 1793.31,-462.6 2267.17,-458.92 -1830.71,-452.76 1251.75,-452.36 848.79,-451.56 2153.32,-437.64 -2933.07,-433.07 -2539.37,-433.07 -2005,-429.68 -2315.81,-428.51 -484.85,-418.8 -131.77,-417.85 68.23,-417.85 268.23,-417.85 368.23,-417.85 2568.23,-417.85 2285.26,-416.36 -354.33,-413.39 2233.11,-382.48 -1751.97,-374.02 -728.35,-374.02 -533.54,-358.8 -2539.37,-354.33 -2305.29,-346.72 2195.88,-345.06 -1980.46,-344.38 -692.96,-338.48 883.61,-328.45 -231.77,-317.85 -31.77,-317.85 168.23,-317.85 368.23,-317.85 2668.23,-317.85 -2933.07,-314.96 -354.33,-314.96 697.53,-313.62 -2775.59,-295.28 -1673.23,-295.28 -956.16,-295.68 2336.34,-291.86 1522.64,-284.99 1603.82,-285.37 -2500,-275.59 2452.32,-275.9 -1125.66,-255.08 -863.08,-251.81 -1614.17,-216.54 -2933.07,-196.85 2342.72,-187.58 2489.56,-185.45 -1881.93,-170.91 -720.78,-159.8 674.24,-143.92 852.89,-141.27 976.92,-138.56 -1515.75,-137.8 -2472.44,-122.05 -231.77,-117.85 -31.77,-117.85 168.23,-117.85 368.23,-117.85 1784.56,-101.06 745.98,-99.65 -2500,-98.43 -728.35,-98.43 -531.5,-98.43 -354.33,-98.43 -1087.07,-92.45 -955.83,-88.22 842.3,-62.83 -1437.01,-59.06 955.83,-56.78 687.98,-53.85 -878.34,-51.77 1448.71,-50.97 2622.05,-51.18 1177.17,-47.24 -1870.75,-28.3 -2995.05,-24.01 -131.77,-17.85 68.23,-17.85 268.23,-17.85 468.23,-17.85 601.53,-13.62 1610.24,-7.87 1787.4,-7.87 -531.5,0 -354.33,0 -1358.27,19.68 834.81,19.81 899.13,31.03 736.82,31.63 1225.46,33.34 -728.35,35.43 -1850.39,39.37 -1712.6,39.37 1081.58,45.9 1372.51,49.43 -2818.04,50.52 671.19,53 2354.33,55.12 2493.65,59.52 2323.4,60.58 1890.7,69.28 1610.24,70.87 1757.18,73.35 -1021.45,81.13 -876.06,82.05 -231.77,82.15 -31.77,82.15 168.23,82.15 368.23,82.15 2140.39,90.98 -1673.23,98.43 -1279.53,98.43 -728.35,98.43 -531.5,98.43 -354.33,98.43 837.83,98.37 924.17,112.19 2411.72,113.78 1107.64,136.6 2186.6,143.92 739.88,144.59 1614.17,149.61 1757.18,150.61 -2933.07,157.48 -2795.28,157.48 841.92,172.25 2500.04,173.37 928.81,175.55 -2106.3,181.1 -131.77,182.15 68.23,182.15 268.23,182.15 468.23,182.15 -728.35,196.85 -531.5,196.85 -354.33,196.85 668.14,198.02 -1850.39,216.54 1188.97,219.29 -874.47,223.76 -969.51,225.28 2362.42,249.63 -1141.73,255.91 660.5,256.02 881.84,257.55 2490.46,260.62 -1673.23,275.59 -1555.12,275.59 -231.77,282.15 -31.77,282.15 168.23,282.15 368.23,282.15 2291.43,284.33 1049.27,287.73 -2933.07,295.28 -2795.28,295.28 -2657.48,295.28 -1850.39,295.28 -873.48,296.06 -728.35,295.28 -531.5,295.28 -354.33,295.28 2402.42,295.63 1618.11,322.83 -1062.99,334.65 603.53,340.38 832.2,343.06 913.07,345.19 -2074.8,354.33 -2125.98,358.27 2306.33,367.94 -1850.39,374.02 -1673.23,374.02 -1555.12,374.02 -1437.01,374.02 -131.77,382.15 68.23,382.15 268.23,382.15 468.23,382.15 2263.78,385.83 -2125.98,393.7 -728.35,393.7 -531.5,393.7 -354.33,393.7 1429.55,398.77 1081.18,400.33 -984.25,413.39 838.59,418.61 -2125.98,429.13 -2933.07,433.07 -2795.28,433.07 -2657.48,433.07 902.43,433.51 952.44,437.76 1622.05,440.94 1481.34,446.78 1722.62,448.82 -1850.39,452.76 -2224.41,464.57 -1673.23,472.44 -1555.12,472.44 -1437.01,472.44 -1318.9,472.44 -31.77,482.15 168.23,482.15 368.23,482.15 2305.47,489.52 -905.51,492.13 -728.35,492.13 -531.5,492.13 -354.33,492.13 2264.87,497.98 1081.18,500.33 1181.18,500.33 1469.91,507.54 1622.05,507.87 938.71,519.29 2305.13,528.18 -2162.12,529.91 -1850.39,531.5 -1531.22,532.1 -1907.08,533.29 -2073.49,534.76 -1184.81,562.24 2304.78,566.16 -2933.07,570.87 -2795.28,570.87 -2657.48,570.87 -1701.71,581.15 -131.77,582.15 68.23,582.15 268.23,582.15 468.23,582.15 -1598.16,589.06 1507.1,588.16 -531.5,590.55 -354.33,590.55 1623.67,590.87 -2160.66,592.39 -2072.52,594.33 -1665.35,594.49 -1838.58,598.43 1081.18,600.33 1181.18,600.33 1281.18,600.33 2305.13,607.58 1551.21,617.91 -1637.8,618.11 607.53,618.38 -2387.44,619.62 -1909.45,629.92 2408.55,643.01 1093.04,651.39 2459.38,652.99 -2070.1,662.13 1421.25,668.91 -31.77,682.15 168.23,682.15 368.23,682.15 -531.5,692.91 1555.37,692.41 1644.68,694.56 -354.33,696.85 -2933.07,708.66 -1909.45,708.66 2551.66,717.12 -2303.15,728.35 -669.61,728.29 1656.71,752.21 1742.71,753.51 969.92,756 2453.45,778.97 -1909.45,787.4 607.53,788.38 -531.5,807.09 -354.33,807.09 -2303.15,826.77 1736.22,834.65 -137.8,846.46 59.06,846.46 275.59,846.46 1589.96,849.39 -1909.45,866.14 1660.52,871.05 -2184.31,871.63 -2047.78,872.94 -2432.74,873.31 368.23,882.15 -621.8,891.76 951.27,909.79 1040.71,909.35 -1108,911.62 848.96,915.41 -1673.23,925.2 -1397.64,925.2 -354.33,925.2 -456.69,929.13 -1562.29,942.84 -1909.45,944.88 -39.37,944.88 2174,955.02 -562.99,956.69 609.53,956.38 -719.04,959.21 -1267.85,962.92 2128.87,982.71 -446.23,993.23 -2814.96,1003.94 -2578.74,1003.94 -2440.94,1003.94 -2303.15,1003.94 -2165.35,1003.94 -2027.56,1003.94 -1673.23,1003.94 -1397.64,1003.94 -1136.32,1007.71 -562.99,1035.43 -719.99,1036.22 1270.53,1038.52 -1145.67,1039.37 -137.8,1043.31 59.06,1043.31 275.59,1043.31 -1888.07,1057.32 -1615.82,1060.32 2179.26,1061.42 1307.53,1070.92 -1436.63,1074.45 -374.02,1086.61 -299.21,1086.61 -1584.24,1100.6 -2303.15,1102.36 -1712.48,1102.8 -1407.7,1103.68 -1643.53,1105.44 -562.99,1114.17 1794.6,1114.08 1082.29,1119.54 1680.87,1119.98 551.18,1125.98 590.55,1125.98 -444.8,1126.66 827.53,1132.89 1359.09,1132.81 1399.09,1132.81 1439.09,1132.81 -230.7,1137.78 -746.4,1141.56 1359.09,1172.81 1399.09,1172.81 1439.09,1172.81 -813.49,1175.63 1114.83,1185.42 -847.88,1189.24 -755.31,1195.55 1835.74,1206.02 1046.35,1210.7 1359.09,1212.81 1399.09,1212.81 1439.09,1212.81 -1712.92,1216.98 2169.29,1216.54 915.54,1218.95 -1955.94,1222.07 -1433.17,1226.76 -1583.67,1234.98 -2799.39,1244.27 -941.79,1249.17 2169.29,1251.97 -1338.3,1254.13 -2940.41,1255.34 1078.22,1255.2 -203.53,1267.2 1834.42,1270.03 864.86,1270.8 2575.5,1270.39 -2856.98,1273.8 1111.7,1275.7 -298.74,1277.92 220.26,1281.71 505.7,1283.04 568.23,1282.15 1499.8,1282.76 2668.23,1282.15 425.2,1283.46 1020.42,1286.12 1683.06,1297.88 1729.41,1301.03 1798.59,1300.81 2604.02,1301 370.08,1311.02 -2481.45,1314.46 2439.42,1314.32 -2542.61,1315.37 1136.56,1317.8 2605.02,1334.61 -1563.72,1336.56 849.54,1345.05 1078.22,1355.2 -2913.39,1358.27 -2814.96,1358.27 -2696.85,1358.27 -2618.11,1358.27 1135.96,1359.41 1662.31,1373.1 2354.33,1374.02 2618.43,1375.82 -2512.37,1376.99 2668.23,1382.15 1748.03,1385.83 1001.57,1388.66 927.32,1394.55 1684.53,1398.1 2047.24,1401.57 2354.33,1401.57 370.08,1409.45 823.69,1412.23 2617.23,1412.43 1078.74,1413.39 1656.11,1413.83 118.11,1417.32 196.85,1417.32 -1902.36,1419.94 1358.27,1429.13 1732.28,1433.07 2603.64,1456.66 1000,1460.63 1822.83,1460.63 1787.4,1464.57 941.38,1470.82 1376.88,1470.68 1074.8,1476.38 2668.23,1482.15 2246.73,1485.43 2605.22,1492.21 118.11,1496.06 19.69,1515.75 -1755.91,1523.62 389.76,1527.56 -175.4,1535.38 2283.52,1543.38 -1765.05,1557.97 -1799.21,1562.99 1472.44,1562.99 -1451.56,1566.48 1700.79,1566.93 -2618.11,1574.8 118.11,1574.8 -1631.77,1582.15 1204.72,1582.68 1368.23,1582.15 1868.23,1582.15 2468.23,1582.15 2568.23,1582.15 2668.23,1582.15 685.04,1586.61 947.44,1587.46 -428.34,1588.95 -390.61,1588.64 -350.61,1588.64 -1759.84,1590.55 2047.24,1590.55 -2362.2,1594.49 -2204.72,1594.49 1114.17,1594.49 -1580.08,1604.02 -1264.17,1604.24 -1157.19,1605.44 -1204.47,1606.64 893.16,1608.7 766.67,1609.9 722.05,1610.96 851.04,1611.97 -154.22,1617.52 2756.67,1618.99 1313.11,1627.03 -427.95,1628.05 -390.61,1628.64 -350.61,1628.64 -1948.82,1633.86 -1625.39,1641.72 -860.72,1642.97 1204.72,1657.48 -350.61,1668.64 -1264.87,1673.82 -1799.21,1677.17 -1755.91,1677.17 -1308.46,1678.25 -151.11,1679.44 -1027.51,1680.9 1368.23,1682.15 429.13,1685.04 -1095.37,1687.94 1314.96,1688.98 -1159.43,1690.81 -2618.11,1692.91 -2342.52,1692.91 -2204.72,1692.91 -55.43,1693.5 -1830.71,1700.79 566.93,1704.72 2501.86,1704.89 1204.72,1724.41 -655.31,1726.38 -1554.31,1728.76 433.07,1732.28 -1309.92,1736.85 1834.93,1743.08 -1248.03,1744.09 -1539.22,1754.74 -654.84,1755.4 -1669.49,1757.36 -1096.83,1759.13 -811.75,1772.94 -562.91,1778.04 -1327.16,1779.26 -1247.93,1780.92 2668.23,1782.15 -756.24,1787.38 1204.72,1787.4 -2913.39,1791.34 2459.1,1791.99 630.8,1798.5 -1079.68,1800.31 -1185.17,1809.6 -1023.28,1815.55 -975.28,1815.55 -927.28,1815.55 -892.97,1827.53 -59.06,1830.71 433.07,1830.71 750.76,1831.03 1145.2,1830.36 849.03,1832.39 -1246.96,1833.71 2304.15,1834.36 2334.65,1834.65 2383.98,1835.38 2416.32,1835.18 -1324.53,1837.13 -1775.73,1840.02 -1693.77,1840.45 -1623.95,1840.66 -951.28,1847.55 -2618.11,1850.39 -804.15,1850.49 -738.76,1852.01 -1204.3,1865.43 1566.93,1866.14 -1023.28,1875.55 -975.28,1875.55 -927.28,1875.55 -511.69,1879.01 -434.45,1880.75 2568.23,1882.15 2181.1,1885.83 -1072.9,1888.94 -568.35,1888.69 -2913.39,1889.76 -754.72,1898.39 -795.02,1900.68 82.68,1905.51 -521.86,1907.1 -700.74,1908.28 -169.29,1909.45 -454.54,1910.97 -867.15,1913.22 433.07,1929.13 748.03,1937.01 562.99,1940.94 -1230.38,1942.58 -1599.62,1944.19 -1752.65,1971.03 -1810.95,1971.64 -867.15,1972.75 1732.28,1980.31 2500,1980.31 -3031.77,1982.15 968.23,1982.15 1168.23,1982.15 1568.23,1982.15 -165.35,2007.87 -566.64,2018.41 -714.35,2019.86 -511.81,2023.62 -2618.11,2027.56 -1811.02,2027.56 -1417.32,2027.56 -1232.04,2029.17 -868.31,2032.81 -651.39,2046.49 -610.23,2046.49 -2381.89,2047.24 -2263.78,2047.24 -818.59,2051.22 2440.94,2059.06 -385.2,2060.04 -216.5,2060.04 -1120.45,2070.99 -1060.38,2077.08 -909.83,2081.64 -720.05,2084.51 -78.74,2086.61 452.76,2086.61 -847.78,2109.6 -78.74,2125.98 -426.08,2129.79 -1988.19,2145.67 -1232.04,2149.31 -720.47,2149.61 -263.78,2177.17 768.23,2182.15 968.23,2182.15 1568.23,2182.15 -830.3,2205.41 -496.7,2211.89 -340.34,2211.72 -426.71,2212.37 -3035.43,2259.84 2720.47,2275.59 2468.23,2282.15 -2519.68,2283.46 -2303.15,2283.46 -2086.61,2283.46 -1870.08,2283.46 -78.74,2283.46 157.48,2283.46 275.59,2283.46 -2752.49,2288.55 870.08,2303.15 1070.87,2303.15 1267.72,2303.15 1468.5,2303.15 1669.29,2303.15 1850.39,2303.15 1976.38,2303.15 2074.8,2303.15 2267.72,2303.15
  other v2: 712.6,-1106.3 -712.6,1110.24
GND_485: C59.2 C60.2 D54.1 R72.2 R75.1 R76.1 U9.5 | length 1289.4
  Top w10: C60.2@1480.32,-1089.57 1481.2,-1089.57 C60.2@1481.2,-1088.68
  Top w15: D54.1@1100.29,-1397.64 1100.29,-1191.48 1132.9,-1158.87 1220.28,-1158.87 U9.5@1220.28,-1183.87 ; R76.1@1347.44,-1248.03 1347.44,-1247.63 v1(1370.24,-1247.63) 1392.72,-1247.63 R75.1@1392.72,-1248.03
  Top w20: U9.5@1220.28,-1158.87 1220.28,-1123.5 1248.54,-1095.23 1408.31,-1095.23 C59.2@1429.13,-1074.41 ; R72.2@1358.27,-849.41 1406.79,-849.41 1429.28,-871.9 C59.2@1429.28,-1072.65 ; C60.2@1480.32,-1089.57 1463.4,-1072.65 C59.2@1429.28,-1072.65 ; C59.2@1429.13,-1074.41 1429.13,-1072.65 C59.2@1429.28,-1072.65 ; C59.2@1429.13,-1074.41 1429.28,-1074.26 C59.2@1429.28,-1072.65
  Bottom w15: v1(1100.71,-1247.6) 1235.46,-1247.6 ; 1235.49,-1247.63 v1(1370.24,-1247.63)
GPADC4: D59.2 D59.9 J16.14 U1.155 | length 2258.6
  Top w6: J16.14@-1118.11,-1673.23 -1157.48,-1633.86 -1157.48,-1539.37 -1125.99,-1507.88 D59.9@-1125.99,-1408.38 D59.2@-1125.99,-1374.3 -1125.99,-1208.66 -1204.72,-1129.92 -1204.72,41.86 -1049.74,196.85 U1.155@-787.4,196.85
GPADC5: D59.1 D59.10 J16.13 U1.156 | length 2125.5
  Top w6: J16.13@-1118.11,-1594.49 -1118.11,-1541 -1106.3,-1529.19 D59.10@-1106.3,-1408.38 D59.1@-1106.3,-1374.3 -1106.3,-1204.72 -1192.91,-1118.11 -1192.91,33.24 -1068.67,157.48 U1.156@-787.4,157.48
GPADC6: D58.5 D58.6 J16.12 U1.157 | length 2251.4
  Top w6: J16.12@-1039.37,-1673.23 -1078.74,-1633.86 -1078.74,-1523.62 -1027.56,-1472.44 D58.6@-1027.56,-1408.38 D58.5@-1027.56,-1374.3 -1027.56,-1263.78 -1180.73,-1110.61 -1180.73,25.38 -1063.69,142.42 -819.59,142.42 -795.28,118.11 U1.157@-787.4,118.11
HBIAS: C54.2 R64.2 UA1.2 | length 1708.3
  Top w6: R64.2@-1625.98,1733.27 -1606.13,1713.42 -1606.13,1702.99 -1601.09,1697.95 C54.2@-1582.68,1697.95 ; C54.2@-1582.68,1699.8 C54.2@-1582.68,1697.95 ; v1(-1402.99,1577.47) -1398.89,1577.47 -1398.89,1587.21 -1429.78,1618.11 -1519.68,1618.11 -1582.68,1681.1 C54.2@-1582.68,1697.95 ; UA1.2@-343.31,1721.48 -343.31,1740.05 -334.57,1748.79 -334.57,1799.44 v1(-341.31,1799.72)
  Bottom w6: v1(-1402.99,1577.47) -1395.04,1585.42 -1332.25,1585.42 -1316.69,1569.86 -1055.49,1569.86 -989.99,1504.36 -586.63,1504.36 -479.52,1611.46 -479.52,1728.77 -395.15,1813.14 -354.73,1813.14 v1(-341.31,1799.72)
HCEC: Q3.2 R87.1 U1.39 | length 1513.1
  Top w6: U1.39@787.4,-1062.99 793.44,-1062.99 1105.2,-751.23 1996.35,-751.23 2013.88,-768.76 2013.88,-793.21 Q3.2@2007.5,-793.21 2039.87,-825.57 2039.87,-869.71 2048.11,-877.95 R87.1@2065.95,-877.95
HDMI-5V: D69.2 D71.1 R90.2 R91.2 U14.18 | length 658.4
  Top w6: R90.2@2152.56,-1031.5 R91.2@2152.56,-996.06 2152.56,-951.77 2153.54,-950.79 ; D71.1@2185.29,-917.32 D71.1@2187.29,-917.32 ; U14.18@2342.52,-811.02 U14.18@2388.19,-811.02
  Top w13.78: U14.18@2388.19,-811.02 2409.45,-811.02
  Top w19.68: D69.2@2092.62,-937.01 2125.98,-937.01 2139.76,-950.79 2153.54,-950.79 2179.13,-950.79 2188.98,-940.94 2188.98,-927.32 D71.1@2187.29,-917.32 2187.29,-883.57 2208.66,-862.2 2433.07,-862.2 2444.88,-850.39 2444.88,-822.83 2433.07,-811.02 2409.45,-811.02
  Top w30: D69.2@2087.18,-937.01 D69.2@2092.62,-937.01
HDMI-HCEC: Q3.3 R88.2 U14.13 U16.1 U16.10 | length 548.2
  Top w6: R88.2@1874.02,-833.66 1876.97,-830.71 Q3.3@1927.5,-830.71 1927.5,-796.91 v1(1929.13,-795.28) ; v1(2090.55,-708.66) 2110.24,-708.66 2122.05,-720.47 U16.1@2152.25,-720.47 2201.73,-720.47 2209.6,-712.6 U14.13@2342.52,-712.6
  Bottom w6: v1(1929.13,-795.28) 2003.94,-795.28 v1(2090.55,-708.66)
HHPD: R89.1 R92.1 U1.40 | length 1460.6
  Top w6: U1.40@787.4,-1023.62 814.74,-1023.62 1099.13,-739.23 2005.96,-739.23 R89.1@2065.95,-799.21 R92.1@2065.95,-838.58
HHPD1: R89.2 U14.19 U16.5 U16.6 | length 256.2
  Top w6: R89.2@2099.41,-799.21 U16.5@2152.25,-799.21 2220.47,-799.21 2236.22,-814.96 2267.72,-814.96 2283.46,-830.71 U14.19@2342.52,-830.71
HP-DET: R62.1 RA9.1 RA11.2 RA13.2 | length 1741.5
  Top w6: R62.1@-1452.76,1782.48 -1452.76,1687.95 -1330.68,1565.87 -1065.41,1565.87 -935.86,1436.32 -701.4,1436.32 -702,1436.92 v1(-702.06,1436.86) ; RA13.2@-176.18,1437.01 -176.18,1437.1 v1(-151.36,1437.1) -126.97,1437.1 RA9.1@-126.97,1437.01 ; RA11.2@-176.18,1594.49 -158.05,1594.49 -148.6,1585.03 -148.6,1500.05 v1(-152.06,1496.58)
  Bottom w6: v1(-702.06,1436.86) -700.01,1434.64 -691.91,1442.74 -240.16,1442.74 -231.51,1434.09 -154.37,1434.09 v1(-151.36,1437.1) -151.36,1495.88 v1(-152.06,1496.58)
HP-DET-PE11: RA9.2 U1.129 | length 900.2
  Top w6: U1.129@-629.92,1181.1 -628.72,1168.94 v1(-628.72,1148.85) ; RA9.2@-93.5,1437.01 -70.29,1413.8 v1(-70.29,1392.4)
  Bottom w6: v1(-628.72,1148.85) -560.11,1148.85 -539.93,1169.03 -539.93,1402.82 -528.27,1414.48 -275.21,1414.48 -261.09,1400.36 -82.13,1400.36 v1(-70.29,1392.4)
HPOUTFB-1: D47.2 J11.2 RA32.2 RN1.2 | length 318.1
  Top w6: RA32.2@-1755.91,1815.94 -1754.64,1817.21 D47.2@-1669.29,1817.21 -1669.29,2024.33 -1657.48,2036.14 J11.2@-1657.48,2043.31
HPOUTFB-2: C57.1 CA27.2 R65.1 R68.2 RA32.1 RN2.1 UA1.18 | length 1593.9
  Top w6: RN2.1@-1838.58,1782.48 -1838.58,1744.48 -1827.37,1733.27 R65.1@-1799.21,1733.27 C57.1@-1755.91,1733.27 ; RA32.1@-1755.91,1782.48 C57.1@-1755.91,1733.27 ; R68.2@-1712.6,1650.59 v1(-1712.6,1674.52) CA27.2@-1712.6,1699.8 -1729.33,1716.54 -1739.17,1716.54 C57.1@-1755.91,1733.27 ; v1(-1646.71,1674.38) -1599.58,1674.38 -1522.72,1597.52 v1(-1437.89,1597.52) ; v1(-540.77,1578.54) -537.59,1581.72 UA1.18@-498.82,1581.72
  Bottom w6: v1(-1712.6,1674.52) -1646.85,1674.52 v1(-1646.71,1674.38) ; v1(-1437.89,1597.52) -1327.3,1597.52 -1310.04,1580.26 -1051.75,1580.26 -987.85,1516.36 -591.64,1516.36 -542.6,1565.4 -542.6,1576.7 v1(-540.77,1578.54)
HPOUTL-2: C52.2 UA1.17 | length 994.9
  Top w6: C52.2@-1409.45,1703.74 -1393.56,1703.74 -1386.87,1697.05 -1386.87,1661.77 -1355.92,1630.82 -1124.87,1630.82 v1(-1117.22,1623.17) ; v1(-541.84,1607.2) -532.1,1597.47 UA1.17@-498.82,1597.47
  Bottom w6: v1(-1117.22,1623.17) -1109.2,1631.19 -1049.4,1631.19 -1009.79,1591.58 -557.46,1591.58 v1(-541.84,1607.2)
HPOUTR-2: C53.2 UA1.19 | length 1014.6
  Top w6: C53.2@-1354.33,1703.74 -1370.33,1703.74 -1374.87,1699.2 -1374.87,1667.05 -1350.65,1642.83 -1125.97,1642.83 v1(-1116.75,1652.05) ; v1(-569.62,1611.58) -569.61,1574.68 -553.41,1558.47 -532.53,1558.47 -525.04,1565.97 UA1.19@-498.82,1565.97
  Bottom w6: v1(-1116.75,1652.05) -1107.9,1643.2 -1044.34,1643.2 -1004.72,1603.58 -577.61,1603.58 v1(-569.62,1611.58)
HS-MIC-1: D46.2 J11.5 RA31.2 RN2.2 | length 1080.9
  Top w6: RN2.2@-1838.58,1815.94 RA31.2@-1799.21,1815.94 -1799.21,1872.06 v1(-1799.96,1872.81) ; J11.5@-1381.89,2251.57 -1362.2,2251.57 -1299.21,2188.58 -1299.21,1885.92 v1(-1298.43,1870.95) -1299.21,1870.95 D46.2@-1299.21,1817.21
  Bottom w6: v1(-1799.96,1872.81) -1799.51,1872.81 -1799.51,1870.95 v1(-1298.43,1870.95)
HS-MIC-2: C58.1 CA27.1 R64.1 R66.2 RA31.1 RN1.1 | length 311.4
  Top w6: RA31.1@-1799.21,1782.48 -1785.12,1782.48 -1780.61,1777.97 v1(-1780.61,1758.32) ; RN1.1@-1712.6,1782.48 v1(-1712.59,1758.81) CA27.1@-1712.6,1733.27 -1693.75,1714.42 -1693.75,1707.81 -1685.74,1699.8 C58.1@-1669.29,1699.8 ; R66.2@-1669.29,1650.59 C58.1@-1669.29,1699.8 ; R64.1@-1625.98,1699.8 C58.1@-1669.29,1699.8
  Bottom w6: v1(-1780.61,1758.32) -1712.59,1758.32 v1(-1712.59,1758.81)
HSCL: R90.1 U1.42 U14.15 U16.2 U16.9 | length 2393.2
  Top w6: U1.42@787.4,-944.88 800.54,-958.02 822.91,-958.02 1073.34,-707.59 2018.61,-707.59 2043.31,-732.28 2110.24,-732.28 2118.12,-740.16 U16.2@2152.25,-740.16 2203.21,-740.16 2211.09,-732.28 2267.72,-732.28 2287.4,-751.97 U14.15@2342.52,-751.97 2459.75,-751.97 2511.81,-804.03 2511.81,-962.96 2466.9,-1007.87 2209.65,-1007.87 R90.1@2186.02,-1031.5
HSDA: R91.1 U1.41 U14.16 U16.4 U16.7 | length 2360.7
  Top w6: U1.41@787.4,-984.25 801.6,-970.05 827.94,-970.05 1078.4,-719.59 2006.99,-719.59 2066.93,-779.53 2122.05,-779.53 U16.4@2152.25,-779.53 2222.44,-779.53 2246.06,-755.91 2267.72,-755.91 2283.46,-771.65 U14.16@2342.52,-771.65 2465.29,-771.65 2500,-806.36 2500,-960.63 2464.57,-996.06 R91.1@2186.02,-996.06
HTX0N: U1.45 U14.9 U15.2 U15.9 | length 1655.7
  Top w6: U1.45@787.4,-826.77 797.24,-826.77 812.39,-811.63 836.86,-811.63 1030.84,-617.65 2136.54,-617.65 2140.94,-622.05 U15.2@2152.25,-622.05 2196.15,-622.05 2201.46,-616.74 2275.66,-616.74 2294.81,-635.9 2342.52,-635.9 U14.9@2342.52,-633.86
HTX0P: U1.46 U14.7 U15.1 U15.10 | length 1653.3
  Top w6: U1.46@787.4,-787.4 797.24,-787.4 811.43,-801.59 832.74,-801.59 1026.68,-607.65 2136.3,-607.65 2141.58,-602.36 U15.1@2152.25,-602.36 2197.13,-602.36 2201.47,-606.71 2280.54,-606.71 2294.8,-592.45 2342.52,-592.45 U14.7@2342.52,-594.49
HTX1N: DE1.5 DE1.6 U1.47 U14.6 | length 1643.9
  Top w6: U1.47@787.4,-748.03 797.24,-748.03 812.4,-732.88 843.08,-732.88 1017.35,-558.61 2136.52,-558.61 2140.9,-562.99 DE1.5@2152.25,-562.99 2197.25,-562.99 2201.57,-558.67 2276.64,-558.67 2292.78,-574.8 U14.6@2342.52,-574.8
HTX1P: DE1.4 DE1.7 U1.48 U14.4 | length 1643
  Top w6: U1.48@787.4,-708.66 797.24,-708.66 811.43,-722.85 838.96,-722.85 1013.2,-548.61 2136.04,-548.61 2141.34,-543.31 DE1.4@2152.25,-543.31 2196.7,-543.31 2202.02,-548.64 2279.45,-548.64 2292.65,-535.43 U14.4@2342.52,-535.43
HTX2N: DE1.2 DE1.9 U1.49 U14.3 | length 1639.2
  Top w6: U1.49@787.4,-669.29 797.24,-669.29 812.37,-654.17 851.84,-654.17 1006.44,-499.57 2136.81,-499.57 2141.19,-503.94 DE1.2@2152.25,-503.94 2197.04,-503.94 2202.05,-498.93 2275.96,-498.93 2294.81,-517.79 2342.52,-517.79 U14.3@2342.52,-515.75
HTX2P: DE1.1 DE1.10 U1.50 U14.1 | length 1637.2
  Top w6: U1.50@787.4,-629.92 797.24,-629.92 811.43,-644.11 847.74,-644.11 1002.28,-489.57 2136.41,-489.57 2141.73,-484.25 DE1.1@2152.25,-484.25 2197.14,-484.25 2201.8,-488.91 2280.24,-488.91 2294.81,-474.34 2342.52,-474.34 U14.1@2342.52,-476.38
HTXCN: U1.43 U14.12 U15.5 U15.6 | length 1661
  Top w6: U1.43@787.4,-905.51 797.24,-905.51 812.36,-890.4 836.08,-890.4 1049.73,-676.75 2137.54,-676.75 2141.89,-681.1 U15.5@2152.25,-681.1 2197.11,-681.1 2202.44,-675.77 2275.57,-675.77 2292.72,-692.91 U14.12@2342.52,-692.91
HTXCP: U1.44 U14.10 U15.4 U15.7 | length 1658.5
  Top w6: U1.44@787.4,-866.14 797.24,-866.14 811.43,-880.33 832,-880.33 1045.58,-666.75 2136.39,-666.75 2141.72,-661.42 U15.4@2152.25,-661.42 2197.56,-661.42 2201.9,-665.76 2280.37,-665.76 2292.59,-653.54 U14.10@2342.52,-653.54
